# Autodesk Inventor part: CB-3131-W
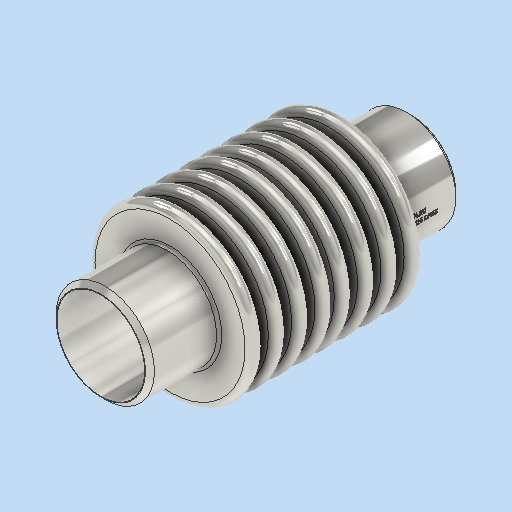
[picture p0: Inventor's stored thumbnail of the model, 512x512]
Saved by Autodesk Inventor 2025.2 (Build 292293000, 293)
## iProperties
Company: DN.RU
Created: 2026-04
Part Number: CB-3131-W
Material: Типовые
Document SubType Name: Modeling
Designer: DN.RU
Density: 5.96524 g/cm^3
Appearance: По умолчанию
Description: D140-02122
Mass: 1500 g
Surface Area: 3561.78 cm^2
Volume: 251.457 cm^3
Author: DN.RU
Title: Компенсатор сильфонный осевой DN.ru Ду65 Ру16
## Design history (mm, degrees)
sketch "Эскиз1"
  geometry: L1 (0, 0)-(0, -120); L2 (38, -120)-(38, 0); L3 (38, 0)-(0, 0); L4 (38, 0)-(38, -7.5); L5 (18, -7.5)-(58, -7.5); L6 (18, -12.5)-(58, -12.5); L7 (58, -2.5)-(18, -2.5); L8 (58, -11.5)-(18, -11.5); L9 (18, -3.5)-(58, -3.5); L10 (58, -20.5)-(18, -20.5); L11 (18, -21.5)-(58, -21.5); L12 (18, -25.5)-(58, -25.5); L13 (18, -30.5)-(58, -30.5); L14 (58, -29.5)-(18, -29.5); L15 (58, -38.5)-(18, -38.5); L16 (18, -39.5)-(58, -39.5); L17 (18, -43.5)-(58, -43.5); L18 (18, -48.5)-(58, -48.5); L19 (58, -47.5)-(18, -47.5); L20 (58, -56.5)-(18, -56.5); L21 (18, -57.5)-(58, -57.5); L22 (18, -61.5)-(58, -61.5); L23 (18, -66.5)-(58, -66.5); L24 (58, -65.5)-(18, -65.5); L25 (0, -120)-(38, -120); L26 (38, -120)-(34, -120); L27 (38, -56.5)-(37, -56.5); L28 (34, -120)-(34, -65.5); L29 (38, -57.5)-(37, -57.5); L30 (37, -57.5)-(37, -47.5); L31 (38, -39.5)-(37, -39.5); L32 (37, -39.5)-(37, -29.5); L33 (38, -21.5)-(37, -21.5); L34 (37, -21.5)-(37, -11.5); L35 (38, -3.5)-(37, -3.5); L36 (37, -3.5)-(37, 0); A1 r 5 centre (18, -7.5) between (18, -2.5) and (18, -12.5); A2 r 5 centre (58, -7.5) between (58, -12.5) and (58, -2.5); A3 r 4 centre (18, -7.5) between (18, -3.5) and (18, -11.5); A4 r 4 centre (58, -7.5) between (58, -11.5) and (58, -3.5); A5 r 4 centre (18, -25.5) between (18, -21.5) and (18, -29.5); A6 r 5 centre (18, -25.5) between (18, -20.5) and (18, -30.5); A7 r 4 centre (58, -25.5) between (58, -29.5) and (58, -21.5); A8 r 5 centre (58, -25.5) between (58, -30.5) and (58, -20.5); A9 r 4 centre (18, -43.5) between (18, -39.5) and (18, -47.5); A10 r 5 centre (18, -43.5) between (18, -38.5) and (18, -48.5); A11 r 4 centre (58, -43.5) between (58, -47.5) and (58, -39.5); A12 r 5 centre (58, -43.5) between (58, -48.5) and (58, -38.5); A13 r 4 centre (18, -61.5) between (18, -57.5) and (18, -65.5); A14 r 5 centre (18, -61.5) between (18, -56.5) and (18, -66.5); A15 r 4 centre (58, -61.5) between (58, -65.5) and (58, -57.5); A16 r 5 centre (58, -61.5) between (58, -66.5) and (58, -56.5); 18 further points
  constraints: 80 end point, 32 point on circle, 16 centre point, 15 point on line, 6 midpoint, 5 perpendicular, 4 tangent, 3 parallel, 2 vertical, 1 horizontal, 69 other
  dimensions: "d0" = 120 distance of L1.start L1.end; "d1" = 38 distance of L2.start L1.end; "d3" = 7.5 distance of L2.end L4.end; "d4" = 20 distance of L4.end L5.end; "d5" = 10 diameter of A2; "d6" = 1 distance between parallel lines of L6 L8; "d9" = 18 distance of L4.end point (38, -25.5); "d14" = 4 distance of L2.start L26.end; "d15" = 1 distance of L27.start L27.end; "d16" = 1 distance of L29.start L29.end; "d17" = 1 distance of L31.start L31.end; "d18" = 1 distance of L33.start L33.end; "d19" = 1 distance of L35.start L35.end
revolve "Вращение1" sketch "Эскиз1" stored, may be unused: angle "d20" = 90 deg
mirror "Зеркальное отражение1"
chamfer "Фаска1" distance "d21" = 3.5; stored, may be unused: second distance "d22" = 2, angle "d23" = 45 deg
fillet "Сопряжение1" dims "d24" = 2
node "РабПлоскость1"
sketch "Эскиз2"
  geometry: L1 (4.495, 11.929)-(4.495, -9.281); L2 (4.495, -9.281)-(-3.635, -9.281); L3 (-3.635, -9.281)-(-3.635, 11.929); L4 (-3.635, 11.929)-(4.495, 11.929); 1 further point
  constraints: 2 other
feature "Рельеф1" sketch "Эскиз2" dims "d25" = 0.1, "d26" = 0
node "Твердое тело1"
node "Эскиз — прямоугольный массив1" dims "d9" = 18, "d12" = 10
